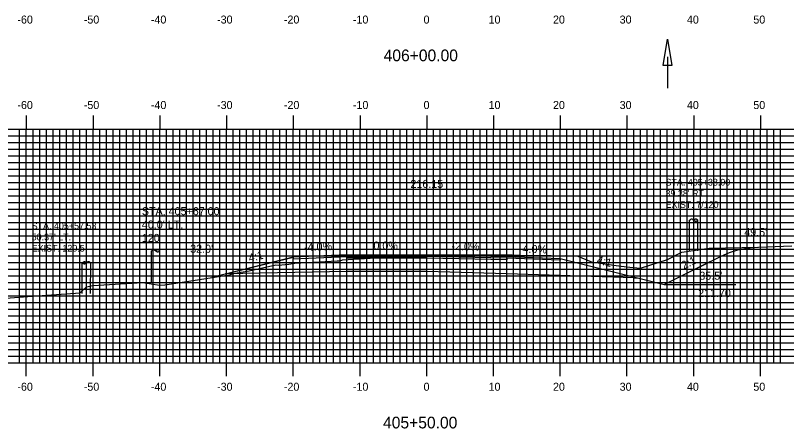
# Model space of a CAD drawing. Extents: x 851742 to 852085, y 364785 to 365005.
# Drawn here: x 851846.1 to 851961.6, y 364848.4 to 364910.3 of the extents above; entities that cross this region are included whole.
import ezdxf

# ---------------------------------------------------------------- set-up
doc = ezdxf.new("R2010")
doc.units = 0
for name, color, linetype in [('ANNOTATION', 7, 'Continuous'), ('D_Drainage_Ditch_Line', 7, 'Continuous'), ('D_Drainage_Text', 7, 'Continuous'), ('D_Roadway_Centerline', 7, 'Continuous'), ('D_Roadway_Centerline_Text', 7, 'Continuous'), ('D_Roadway_Edge_Shoulder', 7, 'Continuous'), ('D_Roadway_Edge_TW', 7, 'Continuous'), ('D_Roadway_Pavement', 7, 'Continuous'), ('D_Roadway_SlopeLines', 7, 'Continuous'), ('D_Roadway_SubGrade', 7, 'Continuous'), ('D_Text_Monospaced', 7, 'Continuous'), ('D_Text_Standard', 7, 'Continuous'), ('D_Utilities_Pole_Joint', 7, 'Continuous'), ('H_V ANNOTATION', 7, 'Continuous'), ('MAJOR', 7, 'Continuous'), ('MINOR', 7, 'Continuous'), ('PDRAIN', 7, 'Continuous'), ('S_Roadway_Centerline', 7, 'Continuous'), ('S_Utilities_Pole_Power', 7, 'Continuous')]:
    doc.layers.add(name, color=color, linetype=linetype)

msp = doc.modelspace()

# ---------------------------------------------------------------- linework, layer by layer
at = {"layer": 'D_Drainage_Ditch_Line'}
msp.add_line((851943.78, 364904.06), (851943.78, 364899.36), dxfattribs=at)
msp.add_lwpolyline([(851944.44, 364902.74), (851943.13, 364902.74), (851943.78, 364906.68)], close=True, dxfattribs=at)
at = {"layer": 'D_Roadway_Edge_Shoulder'}
msp.add_lwpolyline([(851895.7, 364874.38), (851887.7, 364874.06), (851887.7, 364873.81), (851895.7, 364874.13)], close=True, dxfattribs=at)
msp.add_lwpolyline([(851927.7, 364873.82), (851927.7, 364873.57), (851919.7, 364873.89), (851907.7, 364874.13)], dxfattribs=at)
at = {"layer": 'D_Roadway_Edge_TW'}
msp.add_lwpolyline([(851907.7, 364874.13), (851895.7, 364874.13), (851895.7, 364874.38), (851907.7, 364874.38)], dxfattribs=at)
at = {"layer": 'D_Roadway_Pavement'}
for p, q in [((851956.79, 364875.5), (851957.21, 364875.53)), ((851919.7, 364873.9), (851919.7, 364874.14)), ((851938.7, 364870.95), (851939.25, 364870.94))]:
    msp.add_line(p, q, dxfattribs=at)
for points in [[(851907.7, 364873.88), (851895.7, 364873.88), (851895.7, 364874.13), (851907.7, 364874.13)], [(851919.7, 364873.9), (851919.7, 364873.65), (851907.7, 364873.88)]]:
    msp.add_lwpolyline(points, dxfattribs=at)
at = {"layer": 'D_Roadway_SlopeLines'}
for points in [[(851943.25, 364869.94), (851951.79, 364874.21), (851953.04, 364874.76), (851954.29, 364875.16), (851955.54, 364875.4), (851956.79, 364875.5)], [(851887.7, 364874.06), (851875.7, 364871.06), (851875.49, 364870.99)]]:
    msp.add_lwpolyline(points, dxfattribs=at)
at = {"layer": 'D_Roadway_SubGrade'}
for points in [[(851938.7, 364870.95), (851919.7, 364871.52), (851907.7, 364871.88), (851895.7, 364871.88), (851877.53, 364871.52), (851887.7, 364874.06), (851887.7, 364873.81), (851895.7, 364874.13), (851907.7, 364874.13)], [(851907.7, 364874.38), (851919.71, 364874.14), (851927.7, 364873.82), (851943.25, 364869.94), (851950.14, 364873.38)]]:
    msp.add_lwpolyline(points, dxfattribs=at)
at = {"layer": 'D_Utilities_Pole_Joint'}
for p, q in [((851866.45, 364874.99), (851866.61, 364875.1)), ((851866.45, 364870.23), (851866.45, 364874.99)), ((851866.92, 364875.1), (851867.08, 364874.99)), ((851867.24, 364875.1), (851867.08, 364874.99)), ((851867.08, 364874.99), (851867.24, 364874.88)), ((851867.7, 364874.99), (851867.55, 364875.1)), ((851867.55, 364874.88), (851867.7, 364874.99)), ((851867.7, 364870.23), (851867.7, 364874.99))]:
    msp.add_line(p, q, dxfattribs=at)
for centre, start, end in [((851866.77, 364874.88), 90, 125.2644), ((851866.77, 364874.88), 54.7356, 90), ((851867.39, 364874.88), 90, 125.2644), ((851867.39, 364874.88), 54.7356, 90), ((851867.39, 364875.1), 234.7356, 270), ((851867.39, 364875.1), 270, 305.2644)]:
    msp.add_arc(centre, 0.271, start, end, dxfattribs=at)
at = {"layer": 'MAJOR'}
for p, q in [((851847.7, 364895.24), (851847.7, 364893.23)), ((851857.7, 364895.24), (851857.7, 364893.23)), ((851867.7, 364895.24), (851867.7, 364893.23)), ((851877.7, 364895.24), (851877.7, 364893.23)), ((851887.7, 364895.24), (851887.7, 364893.23)), ((851897.7, 364895.24), (851897.7, 364893.23)), ((851907.7, 364895.24), (851907.7, 364893.23)), ((851917.7, 364895.24), (851917.7, 364893.23)), ((851927.7, 364895.24), (851927.7, 364893.23)), ((851937.7, 364895.24), (851937.7, 364893.23)), ((851947.7, 364895.24), (851947.7, 364893.23)), ((851957.7, 364895.24), (851957.7, 364893.23)), ((851767.7, 364893.23), (852047.7, 364893.23)), ((851767.7, 364893.23), (852047.7, 364893.23)), ((851847.7, 364858.23), (851847.7, 364893.23)), ((851857.7, 364858.23), (851857.7, 364893.23)), ((851867.7, 364858.23), (851867.7, 364893.23)), ((851877.7, 364858.23), (851877.7, 364893.23)), ((851887.7, 364858.23), (851887.7, 364893.23)), ((851897.7, 364858.23), (851897.7, 364893.23)), ((851907.7, 364858.23), (851907.7, 364893.23)), ((851917.7, 364858.23), (851917.7, 364893.23)), ((851927.7, 364858.23), (851927.7, 364893.23)), ((851937.7, 364858.23), (851937.7, 364893.23)), ((851947.7, 364858.23), (851947.7, 364893.23)), ((851957.7, 364858.23), (851957.7, 364893.23)), ((851767.7, 364888.23), (852047.7, 364888.23)), ((851767.7, 364883.23), (852047.7, 364883.23)), ((851767.7, 364878.23), (852047.7, 364878.23)), ((851767.7, 364873.23), (852047.7, 364873.23)), ((851767.7, 364868.23), (852047.7, 364868.23)), ((851767.7, 364863.23), (852047.7, 364863.23)), ((851767.7, 364858.23), (852047.7, 364858.23)), ((851767.7, 364858.23), (852047.7, 364858.23)), ((851847.7, 364856.23), (851847.7, 364858.23)), ((851857.7, 364856.23), (851857.7, 364858.23)), ((851867.7, 364856.23), (851867.7, 364858.23)), ((851877.7, 364856.23), (851877.7, 364858.23)), ((851887.7, 364856.23), (851887.7, 364858.23)), ((851897.7, 364856.23), (851897.7, 364858.23)), ((851907.7, 364856.23), (851907.7, 364858.23)), ((851917.7, 364856.23), (851917.7, 364858.23)), ((851927.7, 364856.23), (851927.7, 364858.23)), ((851937.7, 364856.23), (851937.7, 364858.23)), ((851947.7, 364856.23), (851947.7, 364858.23)), ((851957.7, 364856.23), (851957.7, 364858.23))]:
    msp.add_line(p, q, dxfattribs=at)
at = {"layer": 'MINOR'}
for p, q in [((851846.7, 364858.23), (851846.7, 364893.23)), ((851848.7, 364858.23), (851848.7, 364893.23)), ((851849.7, 364858.23), (851849.7, 364893.23)), ((851850.7, 364858.23), (851850.7, 364893.23)), ((851851.7, 364858.23), (851851.7, 364893.23)), ((851852.7, 364858.23), (851852.7, 364893.23)), ((851853.7, 364858.23), (851853.7, 364893.23)), ((851854.7, 364858.23), (851854.7, 364893.23)), ((851855.7, 364858.23), (851855.7, 364893.23)), ((851856.7, 364858.23), (851856.7, 364893.23)), ((851858.7, 364858.23), (851858.7, 364893.23)), ((851859.7, 364858.23), (851859.7, 364893.23)), ((851860.7, 364858.23), (851860.7, 364893.23)), ((851861.7, 364858.23), (851861.7, 364893.23)), ((851862.7, 364858.23), (851862.7, 364893.23)), ((851863.7, 364858.23), (851863.7, 364893.23)), ((851864.7, 364858.23), (851864.7, 364893.23)), ((851865.7, 364858.23), (851865.7, 364893.23)), ((851866.7, 364858.23), (851866.7, 364893.23)), ((851868.7, 364858.23), (851868.7, 364893.23)), ((851869.7, 364858.23), (851869.7, 364893.23)), ((851870.7, 364858.23), (851870.7, 364893.23)), ((851871.7, 364858.23), (851871.7, 364893.23)), ((851872.7, 364858.23), (851872.7, 364893.23)), ((851873.7, 364858.23), (851873.7, 364893.23)), ((851874.7, 364858.23), (851874.7, 364893.23)), ((851875.7, 364858.23), (851875.7, 364893.23)), ((851876.7, 364858.23), (851876.7, 364893.23)), ((851878.7, 364858.23), (851878.7, 364893.23)), ((851879.7, 364858.23), (851879.7, 364893.23)), ((851880.7, 364858.23), (851880.7, 364893.23)), ((851881.7, 364858.23), (851881.7, 364893.23)), ((851882.7, 364858.23), (851882.7, 364893.23)), ((851883.7, 364858.23), (851883.7, 364893.23)), ((851884.7, 364858.23), (851884.7, 364893.23)), ((851885.7, 364858.23), (851885.7, 364893.23)), ((851886.7, 364858.23), (851886.7, 364893.23)), ((851888.7, 364858.23), (851888.7, 364893.23)), ((851889.7, 364858.23), (851889.7, 364893.23)), ((851890.7, 364858.23), (851890.7, 364893.23)), ((851891.7, 364858.23), (851891.7, 364893.23)), ((851892.7, 364858.23), (851892.7, 364893.23)), ((851893.7, 364858.23), (851893.7, 364893.23)), ((851894.7, 364858.23), (851894.7, 364893.23)), ((851895.7, 364858.23), (851895.7, 364893.23)), ((851896.7, 364858.23), (851896.7, 364893.23)), ((851898.7, 364858.23), (851898.7, 364893.23)), ((851899.7, 364858.23), (851899.7, 364893.23)), ((851900.7, 364858.23), (851900.7, 364893.23)), ((851901.7, 364858.23), (851901.7, 364893.23)), ((851902.7, 364858.23), (851902.7, 364893.23)), ((851903.7, 364858.23), (851903.7, 364893.23)), ((851904.7, 364858.23), (851904.7, 364893.23)), ((851905.7, 364858.23), (851905.7, 364893.23)), ((851906.7, 364858.23), (851906.7, 364893.23)), ((851908.7, 364858.23), (851908.7, 364893.23)), ((851909.7, 364858.23), (851909.7, 364893.23)), ((851910.7, 364858.23), (851910.7, 364893.23)), ((851911.7, 364858.23), (851911.7, 364893.23)), ((851912.7, 364858.23), (851912.7, 364893.23)), ((851913.7, 364858.23), (851913.7, 364893.23)), ((851914.7, 364858.23), (851914.7, 364893.23)), ((851915.7, 364858.23), (851915.7, 364893.23)), ((851916.7, 364858.23), (851916.7, 364893.23)), ((851918.7, 364858.23), (851918.7, 364893.23)), ((851919.7, 364858.23), (851919.7, 364893.23)), ((851920.7, 364858.23), (851920.7, 364893.23)), ((851921.7, 364858.23), (851921.7, 364893.23)), ((851922.7, 364858.23), (851922.7, 364893.23)), ((851923.7, 364858.23), (851923.7, 364893.23)), ((851924.7, 364858.23), (851924.7, 364893.23)), ((851925.7, 364858.23), (851925.7, 364893.23)), ((851926.7, 364858.23), (851926.7, 364893.23)), ((851928.7, 364858.23), (851928.7, 364893.23)), ((851929.7, 364858.23), (851929.7, 364893.23)), ((851930.7, 364858.23), (851930.7, 364893.23)), ((851931.7, 364858.23), (851931.7, 364893.23)), ((851932.7, 364858.23), (851932.7, 364893.23)), ((851933.7, 364858.23), (851933.7, 364893.23)), ((851934.7, 364858.23), (851934.7, 364893.23)), ((851935.7, 364858.23), (851935.7, 364893.23)), ((851936.7, 364858.23), (851936.7, 364893.23)), ((851938.7, 364858.23), (851938.7, 364893.23)), ((851939.7, 364858.23), (851939.7, 364893.23)), ((851940.7, 364858.23), (851940.7, 364893.23)), ((851941.7, 364858.23), (851941.7, 364893.23)), ((851942.7, 364858.23), (851942.7, 364893.23)), ((851943.7, 364858.23), (851943.7, 364893.23)), ((851944.7, 364858.23), (851944.7, 364893.23)), ((851945.7, 364858.23), (851945.7, 364893.23)), ((851946.7, 364858.23), (851946.7, 364893.23)), ((851948.7, 364858.23), (851948.7, 364893.23)), ((851949.7, 364858.23), (851949.7, 364893.23)), ((851950.7, 364858.23), (851950.7, 364893.23)), ((851951.7, 364858.23), (851951.7, 364893.23)), ((851952.7, 364858.23), (851952.7, 364893.23)), ((851953.7, 364858.23), (851953.7, 364893.23)), ((851954.7, 364858.23), (851954.7, 364893.23)), ((851955.7, 364858.23), (851955.7, 364893.23)), ((851956.7, 364858.23), (851956.7, 364893.23)), ((851958.7, 364858.23), (851958.7, 364893.23)), ((851959.7, 364858.23), (851959.7, 364893.23)), ((851960.7, 364858.23), (851960.7, 364893.23)), ((851767.7, 364892.23), (852047.7, 364892.23)), ((851767.7, 364891.23), (852047.7, 364891.23)), ((851767.7, 364890.23), (852047.7, 364890.23)), ((851767.7, 364889.23), (852047.7, 364889.23)), ((851767.7, 364887.23), (852047.7, 364887.23)), ((851767.7, 364886.23), (852047.7, 364886.23)), ((851767.7, 364885.23), (852047.7, 364885.23)), ((851767.7, 364884.23), (852047.7, 364884.23)), ((851767.7, 364882.23), (852047.7, 364882.23)), ((851767.7, 364881.23), (852047.7, 364881.23)), ((851767.7, 364880.23), (852047.7, 364880.23)), ((851767.7, 364879.23), (852047.7, 364879.23)), ((851767.7, 364877.23), (852047.7, 364877.23)), ((851767.7, 364876.23), (852047.7, 364876.23)), ((851767.7, 364875.23), (852047.7, 364875.23)), ((851767.7, 364874.23), (852047.7, 364874.23)), ((851767.7, 364872.23), (852047.7, 364872.23)), ((851767.7, 364871.23), (852047.7, 364871.23)), ((851767.7, 364870.23), (852047.7, 364870.23)), ((851767.7, 364869.23), (852047.7, 364869.23)), ((851767.7, 364867.23), (852047.7, 364867.23)), ((851767.7, 364866.23), (852047.7, 364866.23)), ((851767.7, 364865.23), (852047.7, 364865.23)), ((851767.7, 364864.23), (852047.7, 364864.23)), ((851767.7, 364862.23), (852047.7, 364862.23)), ((851767.7, 364861.23), (852047.7, 364861.23)), ((851767.7, 364860.23), (852047.7, 364860.23)), ((851767.7, 364859.23), (852047.7, 364859.23))]:
    msp.add_line(p, q, dxfattribs=at)
at = {"layer": 'PDRAIN'}
msp.add_line((851943.25, 364869.94), (851954.02, 364869.94), dxfattribs=at)
at = {"layer": 'S_Roadway_Centerline'}
msp.add_lwpolyline([(851837.99, 364867.41), (851847.95, 364868.16), (851855.75, 364868.71), (851856.73, 364869.61), (851857.68, 364869.81), (851865.15, 364870.26), (851867.66, 364869.83), (851868.46, 364869.92), (851872.68, 364870.53), (851878.07, 364871.41), (851879, 364871.65), (851881.07, 364872.01), (851885.09, 364872.87), (851885.44, 364872.85), (851887.04, 364872.99), (851887.95, 364873.12), (851894.25, 364873.49), (851894.71, 364873.51), (851895.09, 364873.64), (851904.16, 364874.2), (851907.47, 364874.38), (851910.94, 364874.38), (851920.5, 364874.38), (851921.67, 364874.33), (851926.34, 364874.29), (851927.66, 364874.26), (851928.47, 364874.27), (851930.33, 364874.19), (851932.13, 364873.42), (851932.36, 364873.35), (851934.04, 364873.08), (851935.73, 364872.86), (851936.81, 364872.67), (851938.14, 364872.53), (851939.73, 364872.4), (851943.76, 364873.68), (851945.91, 364874.8), (851950.03, 364875.41), (851957.38, 364875.53), (851962.41, 364875.74)], dxfattribs=at)
at = {"layer": 'S_Utilities_Pole_Power'}
for p, q in [((851947.08, 364879.59), (851947.24, 364879.7)), ((851947.08, 364874.97), (851947.08, 364879.59)), ((851947.55, 364879.7), (851947.71, 364879.59)), ((851947.86, 364879.7), (851947.71, 364879.59)), ((851947.71, 364879.59), (851947.86, 364879.48)), ((851948.33, 364879.59), (851948.17, 364879.7)), ((851948.17, 364879.48), (851948.33, 364879.59)), ((851948.33, 364874.97), (851948.33, 364879.59)), ((851856.08, 364873.2), (851856.24, 364873.31)), ((851856.08, 364868.58), (851856.09, 364873.2)), ((851856.24, 364873.09), (851856.08, 364873.2)), ((851856.55, 364873.31), (851856.71, 364873.2)), ((851856.71, 364873.2), (851856.55, 364873.09)), ((851856.86, 364873.31), (851856.71, 364873.2)), ((851857.33, 364873.2), (851857.18, 364873.31)), ((851857.33, 364868.58), (851857.34, 364873.2))]:
    msp.add_line(p, q, dxfattribs=at)
for centre, start, end in [((851947.39, 364879.48), 90, 125.2644), ((851947.39, 364879.48), 54.7356, 90), ((851948.02, 364879.48), 90, 125.2644), ((851948.02, 364879.48), 54.7356, 90), ((851948.02, 364879.7), 234.7356, 270), ((851948.02, 364879.7), 270, 305.2644), ((851856.4, 364873.09), 90, 125.2644), ((851856.4, 364873.31), 234.7356, 270), ((851856.4, 364873.09), 54.7356, 90), ((851856.4, 364873.31), 270, 305.2644), ((851857.02, 364873.09), 90, 125.2644), ((851857.02, 364873.09), 54.7356, 90)]:
    msp.add_arc(centre, 0.271, start, end, dxfattribs=at)

# ---------------------------------------------------------------- texts
at = {"layer": 'ANNOTATION'}
for s, rotation, p in [('-4.0%', 2.2906, (851889.34, 364874.93)), ('-2.0%', 358.8542, (851911.39, 364875.11)), ('-4.0%', 357.7094, (851921.5, 364874.75)), ('4:1', 14.0362, (851881.15, 364873.29)), ('4:1', 345.9638, (851933.09, 364873.1)), ('2:1', 26.5651, (851946.21, 364872.17))]:
    msp.add_text(s, height=1.2, rotation=rotation, dxfattribs=at).set_placement(p)
for s, p in [('0.0%', (851899.71, 364875.18)), ("35.5'", (851948.54, 364870.66)), ('211.70', (851948.36, 364868.06))]:
    msp.add_text(s, height=1.2, dxfattribs=at).set_placement(p)
at = {"layer": 'D_Drainage_Text'}
for s, p in [('STA. 405+67.00', (851865.01, 364880.33)), ("40.0' LT.", (851865.01, 364878.33)), ('120', (851865.01, 364876.32))]:
    msp.add_text(s, height=1.2, dxfattribs=at).set_placement(p)
at = {"layer": 'D_Roadway_Centerline'}
for s in ['C', 'L']:
    msp.add_text(s, height=0.0146, dxfattribs=at).set_placement((851907.7, 364874.38))
at = {"layer": 'D_Roadway_Centerline_Text'}
msp.add_text('216.15', height=1.2, dxfattribs=at).set_placement((851905.25, 364884.41))
at = {"layer": 'D_Text_Monospaced'}
for s, p in [('STA. 405+38.00', (851943.47, 364884.77)), ("39.38' RT.", (851943.47, 364883.1)), ('EXIST. 7/120', (851943.47, 364881.42)), ('STA. 405+57.53', (851848.5, 364878.23)), ("50.37' LT.", (851848.5, 364876.56)), ('EXIST. 120.5', (851848.5, 364874.88))]:
    msp.add_text(s, height=1, dxfattribs=at).set_placement(p)
at = {"layer": 'D_Text_Standard'}
for s, p in [("49.5'", (851955.27, 364877.19)), ("32.0'", (851872.25, 364874.7))]:
    msp.add_text(s, height=1.2, dxfattribs=at).set_placement(p)
at = {"layer": 'H_V ANNOTATION'}
for s, height, p in [('-60', 1.2, (851846.36, 364909.03)), ('-50', 1.2, (851856.31, 364909.03)), ('-40', 1.2, (851866.36, 364909.03)), ('-30', 1.2, (851876.28, 364909.03)), ('-20', 1.2, (851886.29, 364909.03)), ('-10', 1.2, (851896.63, 364909.03)), ('0', 1.2, (851907.22, 364909.03)), ('10', 1.2, (851916.96, 364909.03)), ('20', 1.2, (851926.61, 364909.03)), ('30', 1.2, (851936.6, 364909.03)), ('40', 1.2, (851946.68, 364909.03)), ('50', 1.2, (851956.63, 364909.03)), ('406+00.00', 1.75, (851901.24, 364903.39)), ('-60', 1.2, (851846.36, 364896.23)), ('-50', 1.2, (851856.31, 364896.23)), ('-40', 1.2, (851866.36, 364896.23)), ('-30', 1.2, (851876.28, 364896.23)), ('-20', 1.2, (851886.29, 364896.23)), ('-10', 1.2, (851896.63, 364896.23)), ('0', 1.2, (851907.22, 364896.23)), ('10', 1.2, (851916.96, 364896.23)), ('20', 1.2, (851926.61, 364896.23)), ('30', 1.2, (851936.6, 364896.23)), ('40', 1.2, (851946.68, 364896.23)), ('50', 1.2, (851956.63, 364896.23)), ('-60', 1.2, (851846.36, 364854.03)), ('-50', 1.2, (851856.31, 364854.03)), ('-40', 1.2, (851866.36, 364854.03)), ('-30', 1.2, (851876.28, 364854.03)), ('-20', 1.2, (851886.29, 364854.03)), ('-10', 1.2, (851896.63, 364854.03)), ('0', 1.2, (851907.22, 364854.03)), ('10', 1.2, (851916.96, 364854.03)), ('20', 1.2, (851926.61, 364854.03)), ('30', 1.2, (851936.6, 364854.03)), ('40', 1.2, (851946.68, 364854.03)), ('50', 1.2, (851956.63, 364854.03)), ('405+50.00', 1.75, (851901.15, 364848.39))]:
    msp.add_text(s, height=height, dxfattribs=at).set_placement(p)
at = {"layer": 'S_Roadway_Centerline'}
for s in ['C', 'L']:
    msp.add_text(s, height=0.0146, dxfattribs=at).set_placement((851907.46, 364874.38))

doc.saveas('drawing.dxf')
